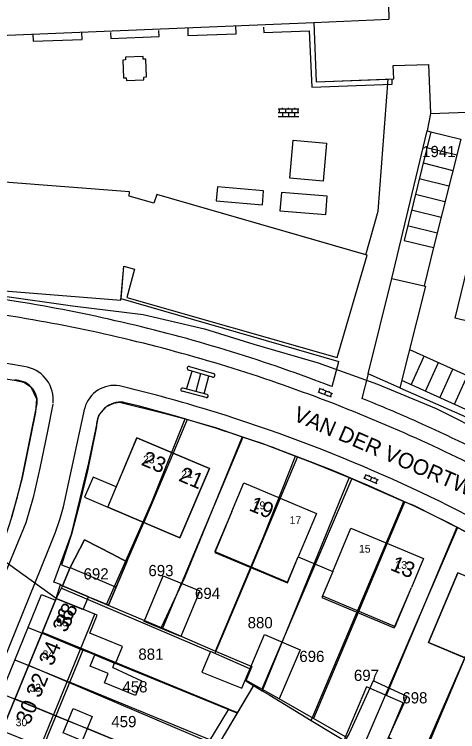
# Model space of a CAD drawing. Extents: x 148816 to 151297, y 399515 to 402500.
# Drawn here: x 150146.7 to 150217.7, y 400509.4 to 400624.4 of the extents above; entities that cross this region are included whole.
import ezdxf

# ---------------------------------------------------------------- set-up
doc = ezdxf.new("R2010")
doc.units = 0
for name, color, linetype in [('B01 Hoofdgebouw  [D] Norm', 7, 'Continuous'), ('B01 Hoofdgebouw  [T] Norm', 7, 'Continuous'), ('B01 hoofgebouw', 7, 'Continuous'), ('B02 Bijgebouw  [D] Norm', 7, 'Continuous'), ('B02 Bijgebouw  [T] Norm', 7, 'Continuous'), ('B07 Tussenmuur  [D] Norm', 7, 'Continuous'), ('G01 perceelsgrens', 7, 'Continuous'), ('S02 Open verharding  Norm', 7, 'Continuous'), ('T04 Haag heg  [D] Gem', 7, 'Continuous'), ('V00 Kant verharding algemeen  [T] Norm', 7, 'Continuous'), ('V00 Kant verharding algemeen secundair  [T] Gem', 7, 'Continuous'), ('Z01 perceelnummer', 7, 'Continuous'), ('Z02 huisnummer', 7, 'Continuous'), ('Z02 Huisnummer  [Tekst] Norm', 7, 'Continuous'), ('Z06 straatnaam', 7, 'Continuous')]:
    doc.layers.add(name, color=color, linetype=linetype)

msp = doc.modelspace()

# ---------------------------------------------------------------- linework, layer by layer
at = {"layer": 'B01 Hoofdgebouw  [D] Norm'}
for p, q in [((150181.49, 400544.66), (150178.76, 400538.14)), ((150178.76, 400538.14), (150190.39, 400533.25)), ((150190.39, 400533.25), (150192.13, 400537.43)), ((150197.65, 400535.08), (150195.9, 400530.93)), ((150207.52, 400526.04), (150210.26, 400532.53)), ((150195.9, 400530.93), (150207.52, 400526.04)), ((150159.93, 400528.08), (150158.02, 400528.86)), ((150158.75, 400525.2), (150159.93, 400528.08)), ((150163.99, 400523.05), (150158.75, 400525.2)), ((150162.89, 400520.35), (150163.99, 400523.05)), ((150157.64, 400522.49), (150151.23, 400506.86)), ((150159.56, 400521.71), (150157.64, 400522.49)), ((150158.82, 400519.9), (150159.56, 400521.71)), ((150159.56, 400521.71), (150162.89, 400520.35)), ((150161.71, 400518.72), (150158.82, 400519.9)), ((150162.43, 400519.71), (150162.72, 400520.42)), ((150162.43, 400519.71), (150167.03, 400517.56)), ((150161.1, 400517.23), (150161.71, 400518.72)), ((150166.06, 400515.2), (150161.1, 400517.23)), ((150167.03, 400517.56), (150166.06, 400515.2))]:
    msp.add_line(p, q, dxfattribs=at)
at = {"layer": 'B01 Hoofdgebouw  [T] Norm'}
for p, q in [((150166.31, 400556.5), (150162.98, 400548.62)), ((150177.9, 400551.59), (150166.31, 400556.5)), ((150173.19, 400540.48), (150177.9, 400551.59)), ((150181.49, 400544.66), (150183.43, 400549.27)), ((150183.43, 400549.27), (150195.07, 400544.38)), ((150161.62, 400545.4), (150173.19, 400540.48)), ((150195.07, 400544.38), (150192.13, 400537.43)), ((150197.65, 400535.08), (150200.58, 400542.03)), ((150200.58, 400542.03), (150212.19, 400537.14)), ((150157.93, 400540.13), (150155.63, 400535.69)), ((150162.37, 400537.83), (150157.93, 400540.13)), ((150192.13, 400537.43), (150197.65, 400535.08)), ((150212.19, 400537.14), (150210.26, 400532.53)), ((150155.63, 400535.69), (150154.4, 400532.75)), ((150213.02, 400523.7), (150217.7, 400534.83)), ((150154.4, 400532.75), (150159.01, 400530.82)), ((150157.7, 400528.99), (150158.53, 400531.02)), ((150153.39, 400530.76), (150144.69, 400509.54)), ((150158.02, 400528.86), (150153.39, 400530.76)), ((150224.64, 400518.8), (150213.02, 400523.7))]:
    msp.add_line(p, q, dxfattribs=at)
for points in [[(150140.34, 400620.81), (150194.61, 400623.07), (150194.99, 400613.56), (150207.44, 400614), (150207.36, 400616.17), (150213.02, 400616.33), (150213.33, 400608.46), (150255.95, 400610), (150255.4, 400625.52)], [(150142.99, 400580.19), (150163.74, 400578.55), (150164.18, 400583.99), (150165.93, 400583.51), (150164.68, 400579), (150198.36, 400569.35), (150203.15, 400585.76), (150169.48, 400595.5), (150168.99, 400594.08), (150165.08, 400595.2), (150165.12, 400595.9), (150144.38, 400597.54)], [(150162.98, 400548.62), (150159.3, 400550.18), (150157.93, 400546.96), (150161.62, 400545.4)]]:
    msp.add_lwpolyline(points, dxfattribs=at)
at = {"layer": 'B01 hoofgebouw'}
for points in [[(150140.34, 400620.81), (150194.61, 400623.07), (150194.99, 400613.56), (150206.54, 400613.97), (150207.44, 400614), (150207.36, 400616.17), (150213.02, 400616.33), (150213.33, 400608.46), (150255.95, 400610), (150255.4, 400625.52)], [(150196.11, 400597.63), (150190.8, 400598.1), (150191.34, 400604.18), (150196.65, 400603.71), (150196.11, 400597.63)], [(150163.74, 400578.55), (150163.76, 400578.79), (150164.18, 400583.99), (150165.93, 400583.51), (150164.68, 400579), (150198.36, 400569.35), (150203.15, 400585.76), (150202.98, 400585.81), (150169.48, 400595.5), (150168.99, 400594.08), (150165.08, 400595.2), (150165.12, 400595.9), (150144.38, 400597.54)], [(150113.52, 400582.03), (150126.86, 400582.49), (150126.69, 400587.33), (150134.14, 400587.59), (150134.13, 400587.97), (150143.55, 400587.22), (150142.99, 400580.19), (150163.74, 400578.55)], [(150207.14, 400582.05), (150212.52, 400580.81), (150208.42, 400564.51), (150203.32, 400566.76), (150207.14, 400582.05)], [(150177.9, 400551.59), (150173.19, 400540.48), (150161.62, 400545.4), (150166.31, 400556.5), (150177.9, 400551.59)], [(150181.49, 400544.66), (150183.43, 400549.27), (150195.07, 400544.38), (150192.13, 400537.43), (150197.65, 400535.08), (150200.58, 400542.03), (150212.19, 400537.14), (150210.26, 400532.53)], [(150181.49, 400544.66), (150178.79, 400538.25), (150190.41, 400533.37), (150192.13, 400537.43)], [(150149.31, 400507.64), (150145.07, 400509.39), (150144.69, 400509.54), (150153.27, 400530.47), (150153.39, 400530.76), (150157.7, 400528.99), (150158.53, 400531.02), (150154.4, 400532.75), (150155.63, 400535.69), (150157.93, 400540.13), (150162.37, 400537.83)], [(150162.37, 400537.83), (150164.71, 400536.61), (150161.76, 400529.65), (150159.01, 400530.82)], [(150197.65, 400535.08), (150196.01, 400531.18), (150207.64, 400526.28), (150210.26, 400532.53)], [(150217.7, 400534.83), (150213.02, 400523.7), (150224.64, 400518.8), (150229.32, 400529.92), (150217.7, 400534.83)], [(150149.31, 400507.64), (150150.88, 400506.99), (150159.58, 400528.22), (150158.02, 400528.86)], [(150217.04, 400502.19), (150206.58, 400508.46), (150209.59, 400515.05), (150204.14, 400517.53), (150200.3, 400509.13), (150197.88, 400505.06), (150203.72, 400501.57)]]:
    msp.add_lwpolyline(points, dxfattribs=at)
at = {"layer": 'B02 Bijgebouw  [D] Norm'}
for p, q in [((150164.71, 400536.61), (150162.37, 400537.83)), ((150155.63, 400535.69), (150162.99, 400532.56)), ((150161.76, 400529.65), (150164.71, 400536.61)), ((150159.01, 400530.82), (150161.76, 400529.65)), ((150183.1, 400516.39), (150186.71, 400524.96)), ((150186.71, 400524.96), (150192.43, 400522.53)), ((150178.06, 400522.23), (150176.72, 400518.95)), ((150184.39, 400519.45), (150178.06, 400522.23)), ((150192.43, 400522.53), (150189.09, 400514.64)), ((150176.72, 400518.95), (150183.1, 400516.39)), ((150189.09, 400514.64), (150183.65, 400517.7)), ((150203.05, 400516.6), (150199.56, 400508.24)), ((150208.92, 400514.04), (150203.05, 400516.6)), ((150205.31, 400505.36), (150208.92, 400514.04)), ((150155.29, 400511.16), (150158.33, 400509.89))]:
    msp.add_line(p, q, dxfattribs=at)
for points in [[(150176.37, 400531.97), (150173.34, 400524.65), (150167.46, 400527.08), (150170.5, 400534.4)], [(150159.13, 400511.82), (150157.52, 400507.96), (150154.49, 400509.23), (150156.1, 400513.09)]]:
    msp.add_lwpolyline(points, close=True, dxfattribs=at)
at = {"layer": 'B02 Bijgebouw  [T] Norm'}
msp.add_lwpolyline([(150196.11, 400597.63), (150190.8, 400598.1), (150191.34, 400604.18), (150196.65, 400603.71), (150196.11, 400597.63)], dxfattribs=at)
msp.add_lwpolyline([(150207.14, 400582.05), (150212.52, 400580.81), (150208.42, 400564.51), (150203.32, 400566.76)], close=True, dxfattribs=at)
at = {"layer": 'B07 Tussenmuur  [D] Norm'}
for p, q in [((150172.11, 400554.04), (150167.4, 400542.93)), ((150172.11, 400554.04), (150167.4, 400542.93)), ((150189.25, 400546.83), (150184.58, 400535.7)), ((150189.25, 400546.83), (150184.58, 400535.7)), ((150206.39, 400539.59), (150201.71, 400528.49)), ((150206.39, 400539.59), (150201.71, 400528.49)), ((150170.4, 400525.87), (150173.43, 400533.18)), ((150170.4, 400525.87), (150173.43, 400533.18)), ((150151.1, 400525.18), (150157.64, 400522.49)), ((150151.1, 400525.18), (150157.64, 400522.49)), ((150189.4, 400523.46), (150186.31, 400516.2)), ((150189.4, 400523.46), (150186.31, 400516.2)), ((150148.98, 400520.01), (150155.52, 400517.33)), ((150148.98, 400520.01), (150155.52, 400517.33)), ((150146.78, 400514.63), (150153.32, 400511.95)), ((150146.78, 400514.63), (150153.32, 400511.95))]:
    msp.add_line(p, q, dxfattribs=at)
at = {"layer": 'G01 perceelsgrens'}
for points in [[(150205.57, 400668.61), (150206.66, 400623.57)], [(150194.61, 400623.07), (150206.66, 400623.57)], [(150194.61, 400623.07), (150194.99, 400613.56), (150207.44, 400614), (150207.36, 400616.17), (150213.02, 400616.33), (150213.33, 400608.46), (150255.95, 400610)], [(150087.21, 400583.23), (150115.48, 400581.32), (150140.46, 400579.49), (150144.74, 400579.23), (150155.97, 400577.67), (150167.31, 400576.23), (150177.11, 400573.96), (150185.05, 400571.48), (150195.33, 400568.49), (150204.82, 400565.09), (150214.21, 400561.21), (150222.69, 400556.92), (150233.05, 400550.87), (150249.68, 400572.16), (150265.04, 400591.86)], [(150140.03, 400566.73), (150141.29, 400566.54), (150146.67, 400565.71), (150148.21, 400565.43), (150149.32, 400564.68), (150150.22, 400562.73), (150150.04, 400560.61), (150147.91, 400550.09), (150146.26, 400543.91), (150144.92, 400539.78)], [(150154.05, 400533), (150152.98, 400533.36), (150155.8, 400541.05), (150158.62, 400552.47), (150160.19, 400560.14), (150161.45, 400561.53), (150162.61, 400562.07), (150163.53, 400562.23), (150170.63, 400560.45), (150174.02, 400559.53)], [(150161.42, 400529.79), (150168.7, 400546.18), (150174.02, 400559.53)], [(150174.02, 400559.53), (150179.02, 400558.12), (150183.14, 400556.64)], [(150183.14, 400556.64), (150173.93, 400534.08), (150170.17, 400526.07)], [(150183.14, 400556.64), (150186.3, 400555.62), (150191.72, 400553.57)], [(150178.91, 400522.3), (150186.52, 400540.49), (150191.72, 400553.57)], [(150191.72, 400553.57), (150194.38, 400552.54), (150200.29, 400550.16)], [(150200.29, 400550.16), (150186.35, 400515.97)], [(150200.29, 400550.16), (150202.95, 400548.97), (150209.06, 400546.3)], [(150194.2, 400511.21), (150209.06, 400546.3)], [(150209.06, 400546.3), (150210.57, 400545.69), (150217.63, 400542.12)], [(150217.63, 400542.12), (150202.25, 400506.4)], [(150217.63, 400542.12), (150220.78, 400540.47), (150225.95, 400537.65)], [(150153.39, 400530.76), (150140.73, 400539.85)], [(150204.92, 400504.94), (150206.63, 400508.25), (150211.95, 400505.44), (150225.95, 400537.65)], [(150153.39, 400530.76), (150154.05, 400533)], [(150154.05, 400533), (150154.4, 400532.75), (150159.01, 400530.82), (150161.42, 400529.79)], [(150151.16, 400525.32), (150153.39, 400530.76)], [(150161.42, 400529.79), (150170.17, 400526.07)], [(150148.99, 400520.03), (150151.16, 400525.32)], [(150181, 400513.03), (150151.16, 400525.32)], [(150170.17, 400526.07), (150178.91, 400522.3)], [(150178.91, 400522.3), (150184.68, 400519.82), (150183.72, 400517.56), (150184.97, 400516.8)], [(150146.78, 400514.64), (150148.99, 400520.03)], [(150177.82, 400507.72), (150148.99, 400520.03)], [(150184.97, 400516.8), (150182.42, 400512.5)], [(150184.97, 400516.8), (150186.35, 400515.97)], [(150186.35, 400515.97), (150187.57, 400515.23), (150194.2, 400511.21)], [(150144.23, 400507.52), (150144.69, 400509.54), (150146.78, 400514.64)], [(150146.78, 400514.64), (150175, 400503)], [(150177.82, 400507.72), (150181, 400513.03)], [(150182.42, 400512.5), (150180.29, 400508.88)], [(150181, 400513.03), (150182.42, 400512.5)], [(150194.2, 400511.21), (150201.2, 400506.97), (150202.25, 400506.4)]]:
    msp.add_lwpolyline(points, dxfattribs=at)
at = {"layer": 'S02 Open verharding  Norm'}
for p, q in [((150188.94, 400609.21), (150192.24, 400609.21)), ((150189.09, 400609.21), (150189.09, 400608.61)), ((150189.59, 400609.21), (150189.59, 400609.36)), ((150190.09, 400609.21), (150190.09, 400608.61)), ((150190.59, 400609.21), (150190.59, 400609.36)), ((150191.09, 400609.21), (150191.09, 400608.61)), ((150191.59, 400609.21), (150191.59, 400609.36)), ((150192.09, 400609.21), (150192.09, 400608.61)), ((150188.94, 400608.61), (150192.24, 400608.61)), ((150188.94, 400608.01), (150192.24, 400608.01)), ((150189.09, 400608.01), (150189.09, 400607.86)), ((150189.59, 400608.61), (150189.59, 400608.01)), ((150190.09, 400608.01), (150190.09, 400607.86)), ((150190.59, 400608.61), (150190.59, 400608.01)), ((150191.09, 400608.01), (150191.09, 400607.86)), ((150191.59, 400608.01), (150191.59, 400608.61)), ((150192.09, 400608.01), (150192.09, 400607.86)), ((150195.41, 400563.81), (150195.62, 400564.37)), ((150195.48, 400564.43), (150197.63, 400563.61)), ((150196.14, 400564.33), (150196.09, 400564.19)), ((150195.27, 400563.87), (150197.42, 400563.04)), ((150195.87, 400563.63), (150195.82, 400563.49)), ((150196.56, 400564.02), (150196.34, 400563.46)), ((150196.81, 400563.28), (150196.76, 400563.14)), ((150197.08, 400563.98), (150197.02, 400563.84)), ((150197.28, 400563.1), (150197.49, 400563.66)), ((150202.74, 400550.03), (150202.98, 400550.58)), ((150202.84, 400550.64), (150204.95, 400549.74)), ((150203.49, 400550.53), (150203.44, 400550.39)), ((150202.6, 400550.09), (150204.72, 400549.19)), ((150203.2, 400549.84), (150203.14, 400549.7)), ((150203.9, 400550.19), (150203.66, 400549.64)), ((150204.12, 400549.45), (150204.06, 400549.31)), ((150204.41, 400550.14), (150204.36, 400550)), ((150204.58, 400549.25), (150204.82, 400549.8))]:
    msp.add_line(p, q, dxfattribs=at)
at = {"layer": 'T04 Haag heg  [D] Gem'}
for p, q in [((150174.36, 400559.41), (150172.11, 400554.04)), ((150183.25, 400556.6), (150173.43, 400533.18)), ((150192.03, 400553.45), (150189.25, 400546.83)), ((150200.72, 400549.98), (150189.4, 400523.46)), ((150209.19, 400546.27), (150206.39, 400539.59)), ((150164.71, 400536.61), (150167.4, 400542.94)), ((150217.54, 400542.17), (150206.24, 400515.21)), ((150184.58, 400535.7), (150178.79, 400521.91)), ((150154.21, 400532.4), (150178.04, 400522.23)), ((150201.71, 400528.49), (150194.58, 400511.5)), ((150148.88, 400526.09), (150151.1, 400525.18)), ((150146.76, 400520.92), (150148.98, 400520.01)), ((150218.81, 400521.25), (150212.06, 400505.17)), ((150182.33, 400512.38), (150162.89, 400520.35)), ((150178.27, 400508), (150155.52, 400517.33)), ((150185.04, 400516.92), (150179.46, 400507.56)), ((150144.56, 400515.54), (150146.78, 400514.63)), ((150199.71, 400508.56), (150189.09, 400514.64)), ((150153.32, 400511.95), (150155.29, 400511.14)), ((150175.2, 400502.98), (150158.33, 400509.89))]:
    msp.add_line(p, q, dxfattribs=at)
for points in [[(150202.98, 400585.81), (150204.92, 400592.82), (150206.54, 400613.97)], [(150198.68, 400568.68), (150163.76, 400578.79)], [(150208.42, 400564.51), (150218.48, 400560.07), (150221.45, 400558.64), (150233.42, 400552.36), (150235.73, 400555.38)]]:
    msp.add_lwpolyline(points, dxfattribs=at)
at = {"layer": 'V00 Kant verharding algemeen  [T] Norm'}
for p, q in [((150207.14, 400582.05), (150212.8, 400605.68)), ((150203.32, 400566.76), (150202.33, 400562.82)), ((150177.55, 400563.42), (150173.68, 400564.43)), ((150177.4, 400562.95), (150173.52, 400563.96)), ((150147.91, 400550.09), (150150.33, 400562.02)), ((150166.48, 400561.61), (150164.17, 400562.18)), ((150152.83, 400561.89), (150151.98, 400557.57)), ((150154.54, 400545.45), (150157.94, 400561.27)), ((150172.54, 400559.96), (150166.48, 400561.61)), ((150178.59, 400558.13), (150172.54, 400559.96)), ((150151.98, 400557.57), (150150.77, 400551.63)), ((150159.81, 400558.29), (150158.36, 400551.22)), ((150150.77, 400551.63), (150149.66, 400546.94)), ((150158.36, 400551.22), (150157.14, 400546.13)), ((150147.15, 400547.05), (150147.91, 400550.09)), ((150205.39, 400547.97), (150203.21, 400548.92)), ((150146.26, 400543.91), (150147.15, 400547.05)), ((150210.95, 400545.42), (150205.39, 400547.97)), ((150149.66, 400546.94), (150148.51, 400542.88)), ((150157.14, 400546.13), (150155.8, 400541.05)), ((150153.97, 400543.42), (150154.54, 400545.45)), ((150216.32, 400542.79), (150210.95, 400545.42)), ((150148.51, 400542.88), (150144.93, 400534.17)), ((150153.25, 400541.37), (150153.97, 400543.42)), ((150152.1, 400538.41), (150153.25, 400541.37)), ((150155.8, 400541.05), (150154.2, 400536.16)), ((150140.99, 400511.11), (150152.1, 400538.41)), ((150154.2, 400536.16), (150155.59, 400535.62)), ((150154.4, 400532.75), (150153.39, 400530.76)), ((150142.48, 400510.46), (150151.04, 400531.37)), ((150151.04, 400531.37), (150153.28, 400530.47))]:
    msp.add_line(p, q, dxfattribs=at)
for points in [[(150162.08, 400621.45), (150162.1, 400620.51), (150169.87, 400620.8), (150169.83, 400621.77)], [(150174.43, 400622.23), (150174.48, 400620.96), (150182.18, 400621.25), (150182.12, 400622.55)], [(150186.57, 400622.3), (150186.61, 400621.43), (150193.91, 400621.72), (150194.29, 400612.71), (150207.19, 400613.16), (150207.18, 400613.99)], [(150149.63, 400621.19), (150149.66, 400620.06), (150157.55, 400620.35), (150157.5, 400621.52)], [(150167.43, 400613.88), (150167.42, 400614.31), (150167.85, 400614.33), (150167.74, 400617.16), (150167.31, 400617.15), (150167.3, 400617.6), (150164.48, 400617.49), (150164.49, 400617.05), (150164.05, 400617.02), (150164.17, 400614.21), (150164.6, 400614.21), (150164.61, 400613.77), (150167.43, 400613.88)], [(150213.34, 400608.46), (150212.8, 400605.68), (150213.35, 400605.55), (150209.1, 400588.11), (150213.78, 400586.97), (150212.32, 400580.86)], [(150186.59, 400596.05), (150179.19, 400596.69), (150179, 400594.47), (150186.4, 400593.83), (150186.59, 400596.05)], [(150196.79, 400595.2), (150189.43, 400595.79), (150189.19, 400592.86), (150196.56, 400592.27), (150196.79, 400595.2)], [(150174.74, 400567.94), (150178.57, 400566.8)], [(150197.56, 400564.7), (150198.64, 400568.7)], [(150178.4, 400566.2), (150174.57, 400567.34)], [(150236.4, 400558.57), (150233.24, 400554.59), (150208.71, 400565.68)]]:
    msp.add_lwpolyline(points, dxfattribs=at)
for centre, radius, start, end in [((150107.79, 400334.97), 246.52, 77.3455, 85.3594), ((150107.55, 400333.57), 245.46, 77.3995, 85.3389), ((150107.5, 400331.23), 250.23, 69.6156, 77.4695), ((150107.17, 400329.72), 249.29, 69.661, 77.5069), ((150112.06, 400368.69), 202.49, 79.5469, 85.1081), ((150147.5, 400562.59), 5.39, 353.9793, 76.0385), ((150174.66, 400567.63), 0.313, 74.0934, 252.6834), ((150178.48, 400566.5), 0.31, 256.0086, 72.5073), ((150146.84, 400562.22), 3.5, 356.7979, 92.7343), ((150102.2, 400315.34), 266.97, 69.0715, 69.7362), ((150162.64, 400560.02), 4.86, 79.6655, 165.1385), ((150113.91, 400354.64), 215.94, 73.0318, 76.7211), ((150173.55, 400564.21), 0.251, 59.589, 263.3936), ((150177.47, 400563.19), 0.246, 253.242, 69.7407), ((150102.11, 400315.66), 264.24, 65.8821, 69.6912), ((150163.7, 400558.32), 3.89, 83.0836, 180.3952), ((150102.2, 400315.34), 266.97, 65.9091, 67.9709), ((150103.85, 400319.62), 252.38, 66.528, 73.1675), ((150111.98, 400336.12), 244.01, 58.2421, 66.0148), ((150100.08, 400310.74), 259.55, 66.5873, 72.3924), ((150113.48, 400339.12), 238.18, 58.2131, 66.0725), ((150099.06, 400309.78), 263.31, 60.7394, 66.4248), ((150108.51, 400329.35), 239.13, 57.9655, 63.2018)]:
    msp.add_arc(centre, radius, start, end, dxfattribs=at)
at = {"layer": 'V00 Kant verharding algemeen secundair  [T] Gem'}
for p, q in [((150212.74, 400603.04), (150217.53, 400601.86)), ((150212.13, 400600.54), (150216.9, 400599.36)), ((150211.52, 400598.03), (150216.27, 400596.86)), ((150210.91, 400595.52), (150215.64, 400594.36)), ((150210.3, 400593.02), (150215.01, 400591.85)), ((150209.66, 400590.52), (150214.38, 400589.35)), ((150210.24, 400564.99), (150212.32, 400569.59)), ((150212.54, 400563.95), (150214.62, 400568.55)), ((150214.84, 400562.9), (150216.92, 400567.51)), ((150217.14, 400561.86), (150219.22, 400566.48))]:
    msp.add_line(p, q, dxfattribs=at)
for points in [[(150213.35, 400605.55), (150218.16, 400604.36), (150213.78, 400586.97)], [(150231.37, 400569.57), (150221.47, 400572.02), (150222.07, 400574.48), (150217.27, 400575.69), (150219.2, 400583.55), (150236.41, 400579.3), (150235.12, 400574.09)], [(150209.97, 400570.65), (150236.49, 400558.68), (150236.4, 400558.57)], [(150174.25, 400564.28), (150175.15, 400567.16)], [(150176.48, 400566.77), (150175.73, 400563.89)], [(150177.07, 400563.54), (150177.81, 400566.38)]]:
    msp.add_lwpolyline(points, dxfattribs=at)

# ---------------------------------------------------------------- texts
at = {"layer": 'Z01 perceelnummer'}
for s, p in [('1941', (150211.98, 400601.48)), ('692', (150157.75, 400533.79)), ('693', (150168.14, 400534.32)), ('694', (150175.6, 400530.67)), ('880', (150184.03, 400525.97)), ('881', (150166.53, 400520.92)), ('696', (150192.31, 400520.57)), ('697', (150201.05, 400517.53)), ('458', (150163.98, 400515.69)), ('698', (150208.81, 400513.93)), ('459', (150162.2, 400510.12))]:
    msp.add_text(s, height=1.8, dxfattribs=at).set_placement(p)
at = {"layer": 'Z02 huisnummer'}
for s, rotation, p in [('23', 337.0496, (150166.85, 400552.2)), ('21', 337.0496, (150172.84, 400549.66)), ('19', 337.2303, (150184.1, 400544.92)), ('13', 337.1775, (150206.73, 400535.37)), ('38', 67.6666, (150155.46, 400525.92)), ('36', 67.7196, (150154.98, 400525.17)), ('34', 67.7196, (150152.8, 400519.8)), ('32', 67.7196, (150150.76, 400514.68)), ('30', 67.6666, (150149.08, 400510.36))]:
    msp.add_text(s, height=2.5, rotation=rotation, dxfattribs=at).set_placement(p)
at = {"layer": 'Z02 Huisnummer  [Tekst] Norm'}
for s, p in [('23', (150167.28, 400552.41)), ('21', (150173.39, 400550.03)), ('19', (150185, 400545.05)), ('17', (150190.75, 400542.68)), ('15', (150201.86, 400538.09)), ('13', (150207.7, 400535.5)), ('36', (150153.35, 400526.3)), ('34', (150151.18, 400521.17)), ('32', (150149.08, 400515.82)), ('30', (150146.88, 400510.28))]:
    msp.add_text(s, height=1.25, dxfattribs=at).set_placement(p)
at = {"layer": 'Z06 straatnaam'}
msp.add_text('VAN DER VOORTWEG', height=2.5, rotation=336.6134, dxfattribs=at).set_placement((150191.18, 400559.35))

doc.saveas('drawing.dxf')
